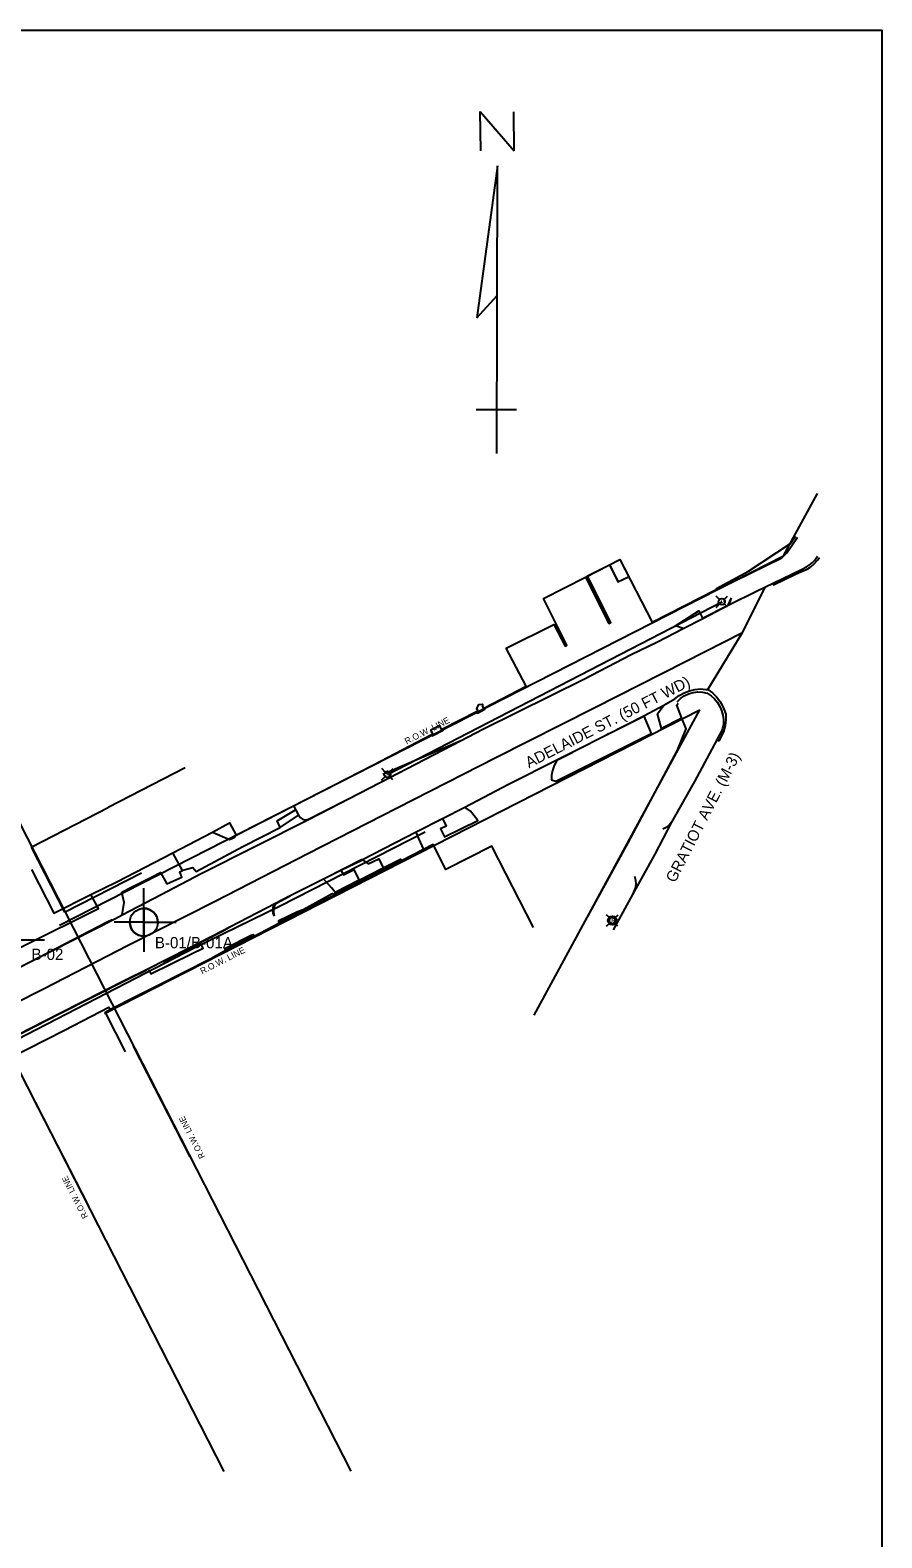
# Model space of a CAD drawing. Extents: x 19007.1 to 19038.2, y 21497.8 to 21516.9.
# Drawn here: x 19030.07 to 19036.48, y 21505.55 to 21516.9 of the extents above; entities that cross this region are included whole.
import ezdxf

# ---------------------------------------------------------------- set-up
doc = ezdxf.new("R2010")
doc.units = 0
for name, color, linetype in [('BORDER', 7, 'Continuous'), ('DETAIL_TEXT_DIMEN_PR', 7, 'Continuous'), ('G-ANNO-TTLB', 7, 'Continuous'), ('Level 14', 7, 'Continuous'), ('TYPICAL_TEXT_DIMEN_PR', 7, 'Continuous'), ('V-ANNO-TEXT', 7, 'Continuous'), ('V-BLDG-OTLN', 7, 'Continuous'), ('V-DEMO-PVMT', 7, 'Continuous'), ('V-PROP-RWAY', 7, 'Continuous'), ('V-PROP-RWAY-IDEN', 7, 'Continuous'), ('V-PVMT-CNTR', 7, 'Continuous'), ('V-PVMT-ROAD', 7, 'Continuous'), ('V-SITE-FENC', 7, 'Continuous'), ('V-SITE-STRS', 7, 'Continuous'), ('V-SITE-WALK', 7, 'Continuous'), ('V-UTIL-OVHD', 7, 'Continuous')]:
    doc.layers.add(name, color=color, linetype=linetype)

msp = doc.modelspace()

# ---------------------------------------------------------------- linework, layer by layer
at = {"layer": 'BORDER'}
for p, q in [((19033.459, 21515.991), (19033.455, 21516.287)), ((19033.455, 21516.287), (19033.71, 21515.991)), ((19033.71, 21515.991), (19033.709, 21516.286)), ((19033.585, 21515.879), (19033.43, 21514.735)), ((19033.579, 21513.713), (19033.585, 21515.879)), ((19033.43, 21514.735), (19033.582, 21514.902)), ((19033.729, 21514.041), (19033.424, 21514.042))]:
    msp.add_line(p, q, dxfattribs=at)
at = {"layer": 'G-ANNO-TTLB'}
msp.add_lwpolyline([(19036.479, 21497.785), (19007.136, 21497.785), (19007.136, 21516.9), (19036.479, 21516.9)], close=True, dxfattribs=at)
at = {"layer": 'Level 14'}
msp.add_circle((19034.45, 21510.195), 0.0328, dxfattribs=at)
at = {"layer": 'TYPICAL_TEXT_DIMEN_PR'}
for p, q in [((19030.922, 21510.182), (19030.922, 21510.44)), ((19030.922, 21510.182), (19030.699, 21510.182)), ((19030.922, 21510.182), (19030.922, 21509.959)), ((19030.922, 21510.182), (19031.166, 21510.182)), ((19029.931, 21510.05), (19030.174, 21510.05))]:
    msp.add_line(p, q, dxfattribs=at)
for points in [[(19030.922, 21510.287), (19030.922, 21510.182), (19031.027, 21510.182)], [(19030.922, 21510.077), (19030.922, 21510.182), (19030.817, 21510.182)]]:
    msp.add_lwpolyline(points, dxfattribs=at)
msp.add_circle((19030.922, 21510.182), 0.105, dxfattribs=at)
for start, end in [(0.0399, 90.0399), (180.0399, 270.0399)]:
    msp.add_arc((19030.922, 21510.182), 0.105, start, end, dxfattribs=at)
at = {"layer": 'V-BLDG-OTLN'}
for points in [[(19030.075, 21510.58), (19030.244, 21510.25), (19030.524, 21510.391), (19030.719, 21510.487), (19031.141, 21510.705), (19031.257, 21510.766), (19031.44, 21510.861), (19031.568, 21510.93), (19031.616, 21510.839), (19032.049, 21511.058), (19032.652, 21511.368), (19033.089, 21511.596), (19033.098, 21511.602), (19033.084, 21511.631), (19033.148, 21511.665), (19033.153, 21511.652), (19033.153, 21511.652), (19033.16, 21511.635), (19033.171, 21511.635), (19033.172, 21511.638), (19033.428, 21511.77), (19033.436, 21511.774), (19033.436, 21511.777), (19033.429, 21511.79), (19033.429, 21511.791), (19033.444, 21511.821), (19033.471, 21511.824), (19033.471, 21511.812), (19033.471, 21511.81), (19033.476, 21511.795), (19033.486, 21511.798), (19033.8, 21511.959), (19033.651, 21512.247), (19034.01, 21512.424), (19034.094, 21512.262), (19034.107, 21512.268), (19033.931, 21512.621), (19034.247, 21512.782), (19034.507, 21512.915), (19034.751, 21512.441), (19035.227, 21512.685)], [(19034.26, 21512.79), (19034.436, 21512.439), (19034.428, 21512.434), (19034.422, 21512.44), (19034.25, 21512.78)], [(19033.856, 21510.143), (19033.543, 21510.755), (19033.196, 21510.58), (19033.101, 21510.767), (19033.029, 21510.731), (19032.861, 21510.645), (19032.367, 21510.392), (19032.357, 21510.387), (19032.09, 21510.25), (19031.949, 21510.177), (19031.938, 21510.172), (19031.752, 21510.075), (19031.738, 21510.068), (19031.542, 21509.971), (19031.426, 21509.908), (19031.021, 21509.702), (19030.875, 21509.628), (19030.67, 21509.524), (19030.63, 21509.502), (19030.781, 21509.206)], [(19032.367, 21510.392), (19032.36, 21510.403), (19032.544, 21510.498), (19032.723, 21510.591), (19032.855, 21510.658), (19032.861, 21510.645)], [(19031.949, 21510.177), (19031.944, 21510.191), (19032.08, 21510.26), (19032.09, 21510.25)], [(19031.542, 21509.971), (19031.535, 21509.984), (19031.732, 21510.08), (19031.738, 21510.068)]]:
    msp.add_lwpolyline(points, dxfattribs=at)
at = {"layer": 'V-DEMO-PVMT'}
for points in [[(19030.757, 21510.409), (19030.828, 21510.446)], [(19028.154, 21508.908), (19028.419, 21509.041), (19028.546, 21509.107), (19028.672, 21509.171), (19029.356, 21509.521), (19030.072, 21509.886), (19030.709, 21510.21), (19030.76, 21510.239), (19031.052, 21510.392)], [(19028.164, 21509.058), (19028.409, 21509.183), (19028.674, 21509.32), (19029.298, 21509.638), (19029.465, 21509.721), (19030.021, 21510.007), (19030.58, 21510.287), (19030.524, 21510.391)], [(19030.76, 21510.239), (19030.775, 21510.331), (19030.757, 21510.409)], [(19028.612, 21509.233), (19028.641, 21509.206), (19028.684, 21509.18), (19029.355, 21509.523), (19030.071, 21509.887), (19030.646, 21510.185), (19030.683, 21510.202)], [(19028.361, 21508.502), (19028.774, 21508.709), (19029.328, 21509.006), (19029.561, 21509.125), (19030.285, 21509.494), (19030.794, 21509.753), (19030.943, 21509.826), (19031.258, 21509.988)], [(19030.96, 21509.824), (19030.974, 21509.794), (19031.28, 21509.945)], [(19031.067, 21509.885), (19031.26, 21509.985)], [(19029.318, 21508.865), (19029.315, 21508.887), (19029.321, 21508.977), (19029.333, 21509.007), (19029.563, 21509.123), (19030.284, 21509.492), (19030.796, 21509.751), (19030.944, 21509.823)]]:
    msp.add_lwpolyline(points, dxfattribs=at)
at = {"layer": 'V-PROP-RWAY'}
for p, q in [((19035.74, 21512.942), (19035.996, 21513.412)), ((19031.526, 21506.047), (19027.866, 21513.207)), ((19028.821, 21513.208), (19032.481, 21506.048)), ((19030.287, 21510.16), (19035.74, 21512.942)), ((19030.626, 21509.495), (19035.11, 21511.782)), ((19033.86, 21509.483), (19035.11, 21511.782)), ((19032.722, 21511.297), (19033.322, 21511.556)), ((19031.233, 21511.344), (19030.653, 21511.046)), ((19030.073, 21510.748), (19030.653, 21511.046)), ((19030.073, 21510.748), (19030.325, 21510.257)), ((19030.325, 21510.257), (19030.905, 21510.554)), ((19031.27, 21508.416), (19030.843, 21509.248)), ((19030.079, 21508.876), (19030.505, 21508.044))]:
    msp.add_line(p, q, dxfattribs=at)
at = {"layer": 'V-PVMT-CNTR'}
msp.add_lwpolyline([(19024.768, 21506.931), (19025.248, 21507.176), (19025.486, 21507.292), (19025.671, 21507.393), (19025.91, 21507.513), (19026.637, 21507.887), (19027.353, 21508.253), (19028.04, 21508.603), (19028.758, 21508.961), (19029.453, 21509.321), (19030.166, 21509.682), (19030.805, 21510.009), (19031.46, 21510.342), (19032.157, 21510.701), (19032.83, 21511.045), (19033.573, 21511.424), (19034.313, 21511.797), (19035, 21512.147), (19035.429, 21512.364)], dxfattribs=at)
at = {"layer": 'V-PVMT-ROAD'}
for points in [[(19031.052, 21510.392), (19031.354, 21510.55), (19032.166, 21510.958), (19032.468, 21511.113), (19032.696, 21511.233), (19033.243, 21511.516), (19033.48, 21511.638), (19034.235, 21512.014), (19034.592, 21512.198), (19034.789, 21512.294), (19034.984, 21512.394), (19035.131, 21512.47), (19035.328, 21512.573), (19035.541, 21512.678), (19035.602, 21512.709), (19035.66, 21512.736), (19035.664, 21512.724), (19035.829, 21512.804), (19035.886, 21512.829), (19035.917, 21512.842), (19035.936, 21512.853), (19035.948, 21512.862), (19035.97, 21512.882), (19035.998, 21512.912), (19036.01, 21512.929)], [(19034.247, 21512.782), (19034.424, 21512.431), (19034.439, 21512.439), (19034.264, 21512.79), (19034.429, 21512.875), (19034.492, 21512.747), (19034.572, 21512.784)], [(19035.662, 21512.736), (19035.879, 21512.84), (19035.911, 21512.859), (19035.942, 21512.88), (19035.957, 21512.892), (19035.971, 21512.906), (19035.979, 21512.916), (19035.994, 21512.938)], [(19035.13, 21512.472), (19035.321, 21512.571), (19035.346, 21512.625)], [(19035.169, 21511.934), (19035.429, 21512.364), (19035.602, 21512.709)], [(19035.328, 21512.575), (19035.34, 21512.602), (19035.346, 21512.625)], [(19031.258, 21509.988), (19031.346, 21510.032), (19031.518, 21510.121), (19031.57, 21510.148), (19031.772, 21510.253), (19031.913, 21510.327), (19032.024, 21510.383), (19032.276, 21510.509), (19032.285, 21510.514), (19032.56, 21510.654), (19032.568, 21510.654), (19032.972, 21510.862), (19033.171, 21510.964), (19033.339, 21511.048), (19033.669, 21511.222), (19034.036, 21511.407), (19034.152, 21511.466), (19034.42, 21511.601), (19034.411, 21511.597), (19034.687, 21511.736), (19034.837, 21511.816), (19034.92, 21511.864), (19034.953, 21511.89), (19034.99, 21511.91), (19035.03, 21511.926), (19035.071, 21511.935), (19035.113, 21511.939), (19035.155, 21511.936), (19035.169, 21511.934), (19035.204, 21511.909), (19035.234, 21511.88), (19035.259, 21511.848), (19035.279, 21511.812), (19035.291, 21511.782), (19035.304, 21511.748), (19035.305, 21511.705), (19035.3, 21511.663), (19035.289, 21511.622), (19035.289, 21511.62), (19035.251, 21511.549), (19035.239, 21511.556)], [(19034.937, 21511.842), (19034.962, 21511.867), (19034.991, 21511.888), (19035.024, 21511.903), (19035.058, 21511.913), (19035.093, 21511.918), (19035.129, 21511.916), (19035.164, 21511.908), (19035.164, 21511.908), (19035.194, 21511.888), (19035.22, 21511.865), (19035.243, 21511.837), (19035.26, 21511.807), (19035.272, 21511.776), (19035.282, 21511.741), (19035.287, 21511.708), (19035.286, 21511.674), (19035.279, 21511.641), (19035.274, 21511.626), (19035.068, 21511.243), (19034.896, 21510.936), (19034.769, 21510.695), (19034.601, 21510.391), (19034.457, 21510.126)], [(19034.974, 21511.719), (19034.82, 21511.642), (19034.791, 21511.752), (19034.837, 21511.816)], [(19034.411, 21511.597), (19034.687, 21511.733), (19034.743, 21511.604)], [(19033.089, 21511.596), (19033.094, 21511.586), (19033.176, 21511.629)], [(19034.036, 21511.405), (19034.152, 21511.464)], [(19031.949, 21510.895), (19031.927, 21510.947), (19032.063, 21511.03)], [(19032.049, 21511.058), (19032.086, 21510.989), (19032.089, 21510.986), (19032.099, 21510.971), (19032.113, 21510.96), (19032.131, 21510.954), (19032.149, 21510.955), (19032.157, 21510.957), (19032.275, 21511.016), (19032.468, 21511.113)], [(19033.171, 21510.964), (19033.199, 21510.906), (19033.157, 21510.886), (19033.186, 21510.825), (19033.436, 21510.949), (19033.382, 21511.019), (19033.348, 21511.042), (19033.339, 21511.048)], [(19031.215, 21510.575), (19031.29, 21510.595), (19031.315, 21510.565), (19031.668, 21510.752), (19031.949, 21510.895), (19032.086, 21510.989)], [(19034.896, 21510.936), (19034.877, 21510.913), (19034.854, 21510.895), (19034.829, 21510.882)], [(19031.44, 21510.861), (19031.567, 21510.806), (19031.602, 21510.82), (19031.616, 21510.839)], [(19032.972, 21510.855), (19032.99, 21510.813), (19033.029, 21510.731)], [(19030.984, 21510.525), (19031.048, 21510.558), (19031.094, 21510.471), (19031.209, 21510.521), (19031.192, 21510.562), (19031.214, 21510.573), (19031.141, 21510.705)], [(19032.285, 21510.514), (19032.405, 21510.574), (19032.569, 21510.653)], [(19032.363, 21510.409), (19032.543, 21510.501), (19032.505, 21510.579)], [(19032.405, 21510.574), (19032.425, 21510.54), (19032.505, 21510.579)], [(19032.569, 21510.653), (19032.612, 21510.622), (19032.691, 21510.659), (19032.723, 21510.591)], [(19030.828, 21510.446), (19030.984, 21510.525)], [(19032.362, 21510.409), (19032.334, 21510.441), (19032.276, 21510.509)], [(19034.617, 21510.53), (19034.624, 21510.5), (19034.626, 21510.469), (19034.621, 21510.438), (19034.61, 21510.409), (19034.601, 21510.391)], [(19031.54, 21509.97), (19031.533, 21509.985), (19031.729, 21510.084), (19031.745, 21510.089), (19031.752, 21510.075), (19031.938, 21510.172), (19031.939, 21510.195), (19032.079, 21510.262), (19032.122, 21510.279), (19032.34, 21510.4), (19032.357, 21510.387)], [(19031.907, 21510.231), (19031.901, 21510.254), (19031.9, 21510.278), (19031.905, 21510.301), (19031.916, 21510.323), (19031.917, 21510.324), (19032.025, 21510.382)], [(19031.906, 21510.229), (19031.897, 21510.25), (19031.894, 21510.272), (19031.897, 21510.294), (19031.905, 21510.315), (19031.913, 21510.327)], [(19032.09, 21510.247), (19032.05, 21510.227)], [(19031.26, 21509.985), (19031.347, 21510.03), (19031.519, 21510.118), (19031.57, 21510.148)], [(19031.28, 21509.945), (19031.369, 21509.988), (19031.347, 21510.03)]]:
    msp.add_lwpolyline(points, dxfattribs=at)
at = {"layer": 'V-SITE-FENC'}
msp.add_lwpolyline([(19035.229, 21512.694), (19035.474, 21512.826), (19035.791, 21513.034), (19035.829, 21513.089)], dxfattribs=at)
at = {"layer": 'V-SITE-STRS'}
for points in [[(19034.494, 21512.751), (19034.43, 21512.877)], [(19034.507, 21512.915), (19034.572, 21512.788)], [(19034.779, 21512.455), (19034.824, 21512.477)], [(19033.436, 21511.774), (19033.436, 21511.777), (19033.429, 21511.79), (19033.429, 21511.791), (19033.444, 21511.821), (19033.471, 21511.824), (19033.471, 21511.812), (19033.471, 21511.81), (19033.476, 21511.795), (19033.48, 21511.795), (19033.484, 21511.797)], [(19033.428, 21511.77), (19033.434, 21511.758), (19033.491, 21511.786), (19033.485, 21511.797)], [(19033.43, 21511.769), (19033.435, 21511.76), (19033.49, 21511.786), (19033.484, 21511.797)], [(19033.098, 21511.602), (19033.096, 21511.607), (19033.09, 21511.619), (19033.089, 21511.62), (19033.084, 21511.631), (19033.148, 21511.665), (19033.153, 21511.652), (19033.153, 21511.652), (19033.16, 21511.635), (19033.171, 21511.635)], [(19033.091, 21511.594), (19033.094, 21511.588), (19033.175, 21511.629), (19033.171, 21511.635)]]:
    msp.add_lwpolyline(points, dxfattribs=at)
at = {"layer": 'V-SITE-WALK'}
for points in [[(19035.229, 21512.684), (19035.49, 21512.812), (19035.725, 21512.926), (19035.764, 21512.963), (19035.845, 21513.082)], [(19034.984, 21512.394), (19034.925, 21512.414), (19035.101, 21512.528), (19035.13, 21512.472)], [(19034.268, 21510.231), (19034.569, 21510.781), (19034.941, 21511.477), (19035.007, 21511.638), (19034.974, 21511.719), (19034.935, 21511.816), (19034.945, 21511.832)], [(19033.991, 21511.254), (19034.025, 21511.245), (19034.487, 21511.475), (19034.743, 21511.604)], [(19034.036, 21511.405), (19034.03, 21511.395), (19034.012, 21511.362), (19033.999, 21511.326), (19033.992, 21511.289), (19033.991, 21511.254)], [(19029.319, 21508.864), (19029.464, 21508.948), (19029.607, 21509.006), (19030.324, 21509.37), (19030.659, 21509.543), (19030.67, 21509.524)]]:
    msp.add_lwpolyline(points, dxfattribs=at)
at = {"layer": 'V-UTIL-OVHD'}
for p, q in [((19035.258, 21512.613), (19035.231, 21512.639)), ((19035.291, 21512.613), (19035.317, 21512.639)), ((19035.231, 21512.553), (19035.258, 21512.579)), ((19035.316, 21512.554), (19035.291, 21512.579)), ((19032.712, 21511.253), (19032.739, 21511.28)), ((19032.739, 21511.313), (19032.713, 21511.339)), ((19032.772, 21511.313), (19032.799, 21511.339)), ((19032.798, 21511.254), (19032.772, 21511.28)), ((19034.433, 21510.212), (19034.407, 21510.238)), ((19034.466, 21510.212), (19034.493, 21510.238)), ((19034.406, 21510.152), (19034.433, 21510.179)), ((19034.491, 21510.154), (19034.466, 21510.179))]:
    msp.add_line(p, q, dxfattribs=at)
for points in [[(19032.756, 21511.296), (19035.274, 21512.596)], [(19026.095, 21507.239), (19026.861, 21507.688), (19027.124, 21507.817), (19027.797, 21508.171), (19029.371, 21508.994), (19031.307, 21509.992), (19031.943, 21510.304), (19033.04, 21510.864)]]:
    msp.add_lwpolyline(points, dxfattribs=at)
for centre in [(19035.274, 21512.596), (19032.756, 21511.296), (19034.45, 21510.195)]:
    msp.add_circle(centre, 0.0239, dxfattribs=at)

# ---------------------------------------------------------------- texts
at = {"layer": 'DETAIL_TEXT_DIMEN_PR'}
for s, p in [('B-01/B-01A', (19031.005, 21509.986)), ('B-02', (19030.076, 21509.898))]:
    msp.add_text(s, height=0.085, rotation=0.0399, dxfattribs=at).set_placement(p)
at = {"layer": 'V-ANNO-TEXT'}
for s, rotation, p in [('ADELAIDE ST. (50 FT WD)', 27.0313, (19033.822, 21511.341)), ('GRATIOT AVE. (M-3)', 62.8066, (19034.922, 21510.474))]:
    msp.add_text(s, height=0.08361, rotation=rotation, dxfattribs=at).set_placement(p)
at = {"layer": 'V-PROP-RWAY-IDEN'}
for height, rotation, p in [(0.04778, 27.0313, (19032.901, 21511.52)), (0.04778, 27.0313, (19031.361, 21509.789)), (0.04535, 117.1686, (19031.384, 21508.416)), (0.04535, 117.1686, (19030.503, 21507.965))]:
    msp.add_text('R.O.W. LINE', height=height, rotation=rotation, dxfattribs=at).set_placement(p)
at = {"layer": 'V-UTIL-OVHD'}
for s, height, p in [('M', 0.0239, (19035.265, 21512.584)), ('M', 0.0239, (19032.747, 21511.284)), ('LB', 0.0275, (19034.428, 21510.182)), ('M', 0.0239, (19034.441, 21510.183))]:
    msp.add_text(s, height=height, rotation=360, dxfattribs=at).set_placement(p)

doc.saveas('drawing.dxf')
